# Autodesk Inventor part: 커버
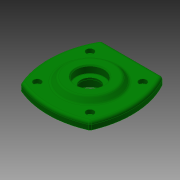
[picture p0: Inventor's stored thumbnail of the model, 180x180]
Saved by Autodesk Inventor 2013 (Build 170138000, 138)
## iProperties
Created: 2016-05
Part Number: 커버
Document SubType Name: Modeling
Designer: mduedu
Density: 2.71 g/cm^3
Material: 알루미늄 6061
Author: mduedu
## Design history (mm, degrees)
sketch "스케치1"
  geometry: L1 (0, 0)-(-37.029, 37.029); L2 (0, 0)-(0, 45); L3 (0, 0)-(45, 0); L4 (32.942, 45)-(-32.942, 45); C1 r 25 at (0, 0); A1 r 90 centre (45, 0) between (-32.942, 45) and (-37.029, -37.029); A2 r 90 centre (0, 45) between (-37.029, -37.029) and (37.029, -37.029); A3 r 90 centre (-45, 0) between (37.029, -37.029) and (32.942, 45); 2 further points
  constraints: 9 point on circle, 8 end point, 4 centre point, 2 horizontal alignment, 2 vertical alignment, 1 coincident, 1 equal radius, 1 horizontal, 1 midpoint, 1 parallel, 1 other
  dimensions: "d28" = 90 distance between centres of A3 A1; "d30" = 50 diameter of C1; "d31" = 45 deg angle of L2 L1; "d33" = 90 distance from line of L4 point (0, -45); "d35" = 45 distance from line of L4 A1.centre (= 0.5 x d33); "d36" = 45 distance from line of L2 A1.centre (= 0.5 x d28)
extrude "돌출1" new body sketch "스케치1" distance "d0" = 8; taper "d1" = 0 deg
extrude "돌출2" join sketch "스케치1" distance "d2" = 12; taper "d3" = 0 deg
sketch "스케치2"
  geometry: C1 r 30 at (0, 0); 1 further point
  constraints: 1 centre point, 1 coincident
  dimensions: "d4" = 60 diameter of C1
extrude "돌출3" join sketch "스케치2" distance "d5" = 5; taper "d6" = -45 deg
sketch "스케치3"
  geometry: C1 r 1.621 at (-28.284, 28.284) reference; C2 r 1.621 at (28.284, 28.284) reference; C3 r 1.621 at (28.284, -28.284) reference; C4 r 1.621 at (-28.284, -28.284) reference; 1 further point
hole "구멍1" sketch "스케치3" at (28.284, 28.284), (-28.284, 28.284), (-28.284, -28.284), (28.284, -28.284) diameter "d7" = 4.5; stored, may be unused: countersink angle "d11" = 90 deg, drill point angle "d13" = 118 deg; dims "d8" = 6, "d9" = 8, "d10" = 4.4, "d12" = 8
fillet "모깎기1" dims "d14" = 3
sketch "스케치4"
  geometry: L1 (-23.757, 13)-(23.757, 13) reference; L2 (25, -12)-(-25, -12) reference; L3 (0, -12)-(0, 13); L4 (-20, -12)-(-20, 0); L5 (-20, 0)-(-15, 0); L6 (-15, 0)-(-15, 3); L7 (-15, 3)-(-10, 3); L8 (-10, 3)-(-10, 5); L9 (-10, 5)-(-15, 5); L10 (-15, 5)-(-15, 13); 1 further point
  constraints: 16 end point, 6 parallel, 2 midpoint, 2 point on line, 1 perpendicular
  dimensions: "d15" = 40 diameter of L4 L3; "d16" = 30 diameter of L10 L3; "d17" = 8 distance of L9.end L10.end; "d18" = 12 distance of L4.start L4.end; "d19" = 3 distance of L5.end L6.end; "d20" = 30 diameter of L6 L3; "d21" = 20 diameter of L8 L3
revolve "회전1" sketch "스케치4" stored, may be unused: angle "d22" = 90 deg
fillet "모깎기2" dims "d23" = 3
fillet "모깎기3" dims "d24" = 0.3
chamfer "모따기1" distance "d25" = 1; stored, may be unused: second distance "d26" = 2, angle "d27" = 45 deg
node "솔리드1"
node "참조2"
node "참조3"
node "참조4"
node "참조5"
